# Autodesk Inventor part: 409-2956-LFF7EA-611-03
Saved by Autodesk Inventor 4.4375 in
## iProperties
Created: 2010-06
Part Number: 409-2956-LFF7EA-611-03
Cost Center: 0 lbmass
Material: A36 STEEL PLATE
Document SubType Name: Sheet Metal
Designer: S. Boerckel
Authority: 0 in^3
Mass: 18161.2 g
Surface Area: 5130.5 cm^2
Volume: 2310.59 cm^3
Density: 7.86 g/cm^3
Flat Pattern Width: 127.077 cm
Flat Pattern Length: 19.05 cm
Flat Pattern Area: 2420.83 cm^2
Sheet Metal Rule: 3/8 HR PLATE
Sheet Metal Width: 39.2500 in
Sheet Metal Length: 174.1719 in^2
Description: PUMP MOUNT STIFFENER
User Status: BURN/BEND
SaveDate: 2008-01-15
SaveTime: 10:24
FileName: Sheet Metal
Wide: =<Flat Pattern Width>cm
Length: =<Flat Pattern Length>cm
Thickness: 0.3750 in
SMR: =<Sheet Metal Rule> - <Material>
Author: S. Boerckel
Revision Number: 0
Subject: DEMIN WATER FORWARDING PUMP SKID-7EA
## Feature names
1. Plate1
2. Plate2
3. Bend1
